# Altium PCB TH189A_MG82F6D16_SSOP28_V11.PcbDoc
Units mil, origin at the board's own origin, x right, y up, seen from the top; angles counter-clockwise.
Board outline 2850.39 x 2110.24 mil, 2 copper layers (Top Layer, Bottom Layer); 46 components, 43 nets, 241 pads, 113 vias.
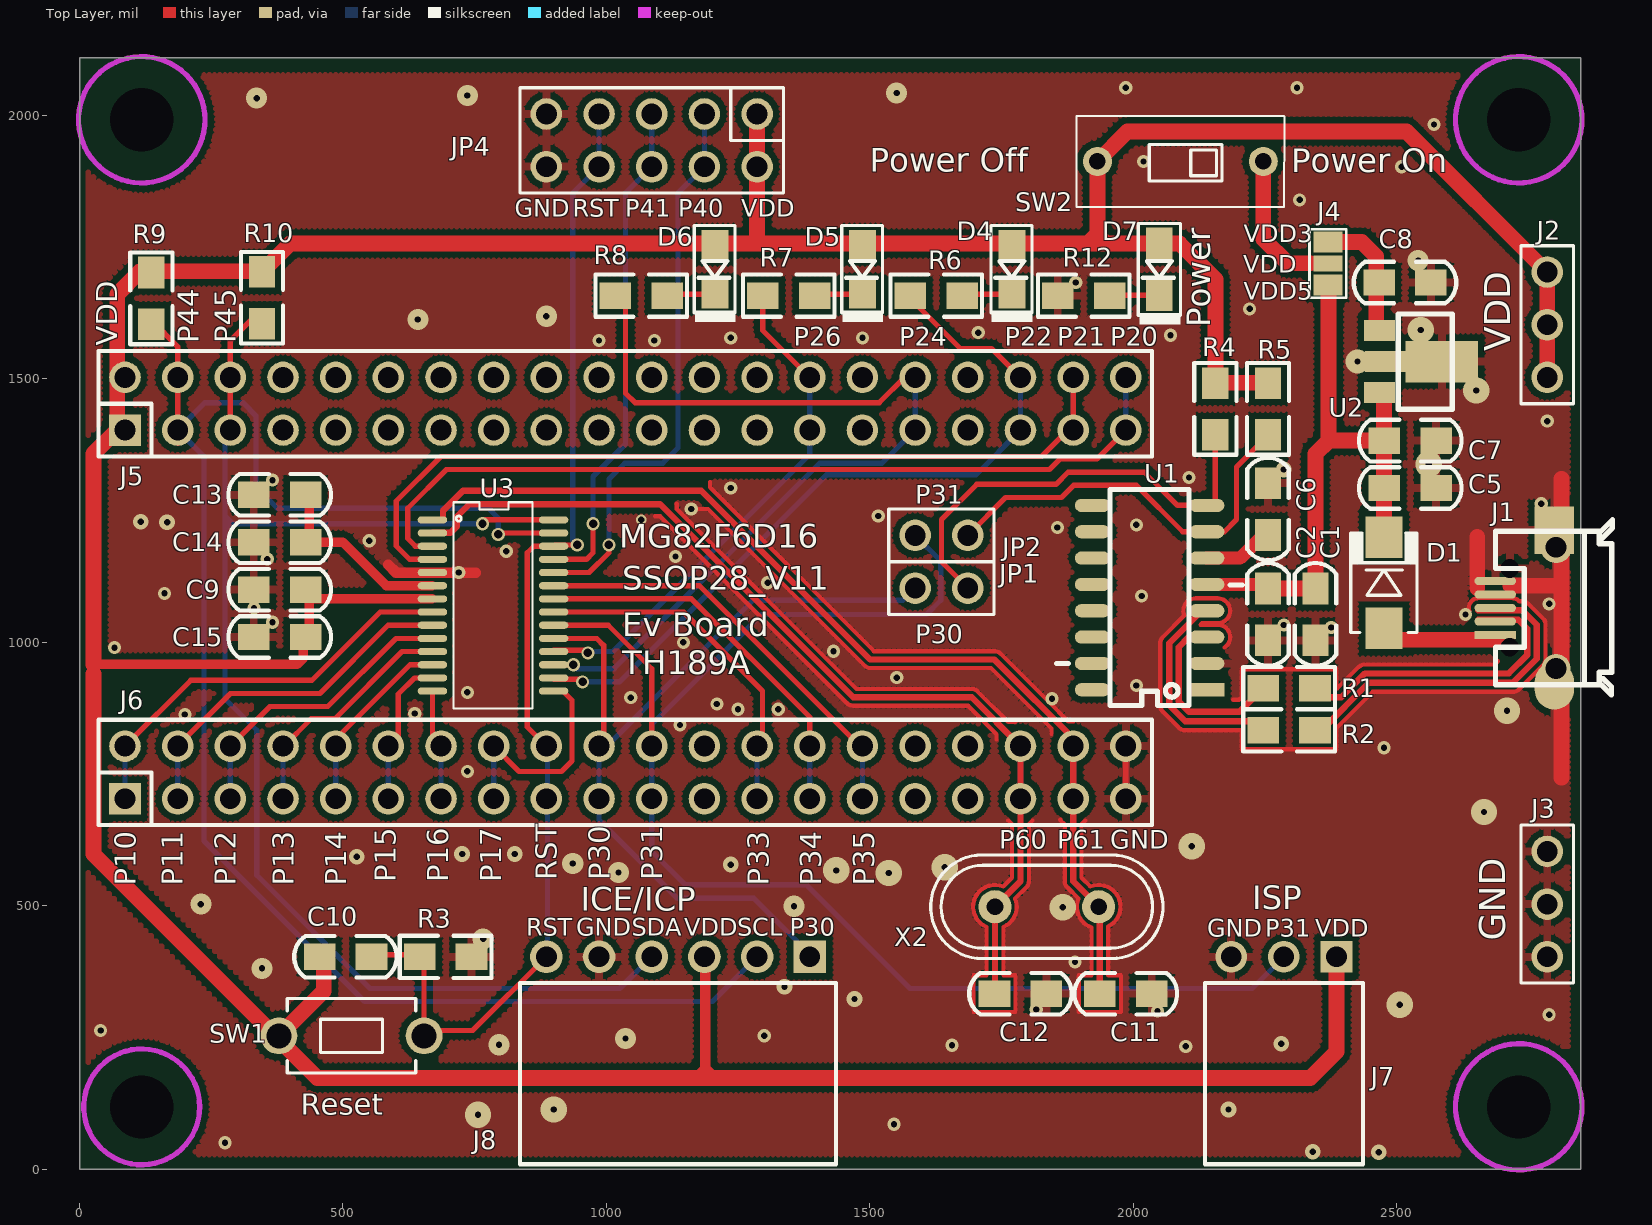
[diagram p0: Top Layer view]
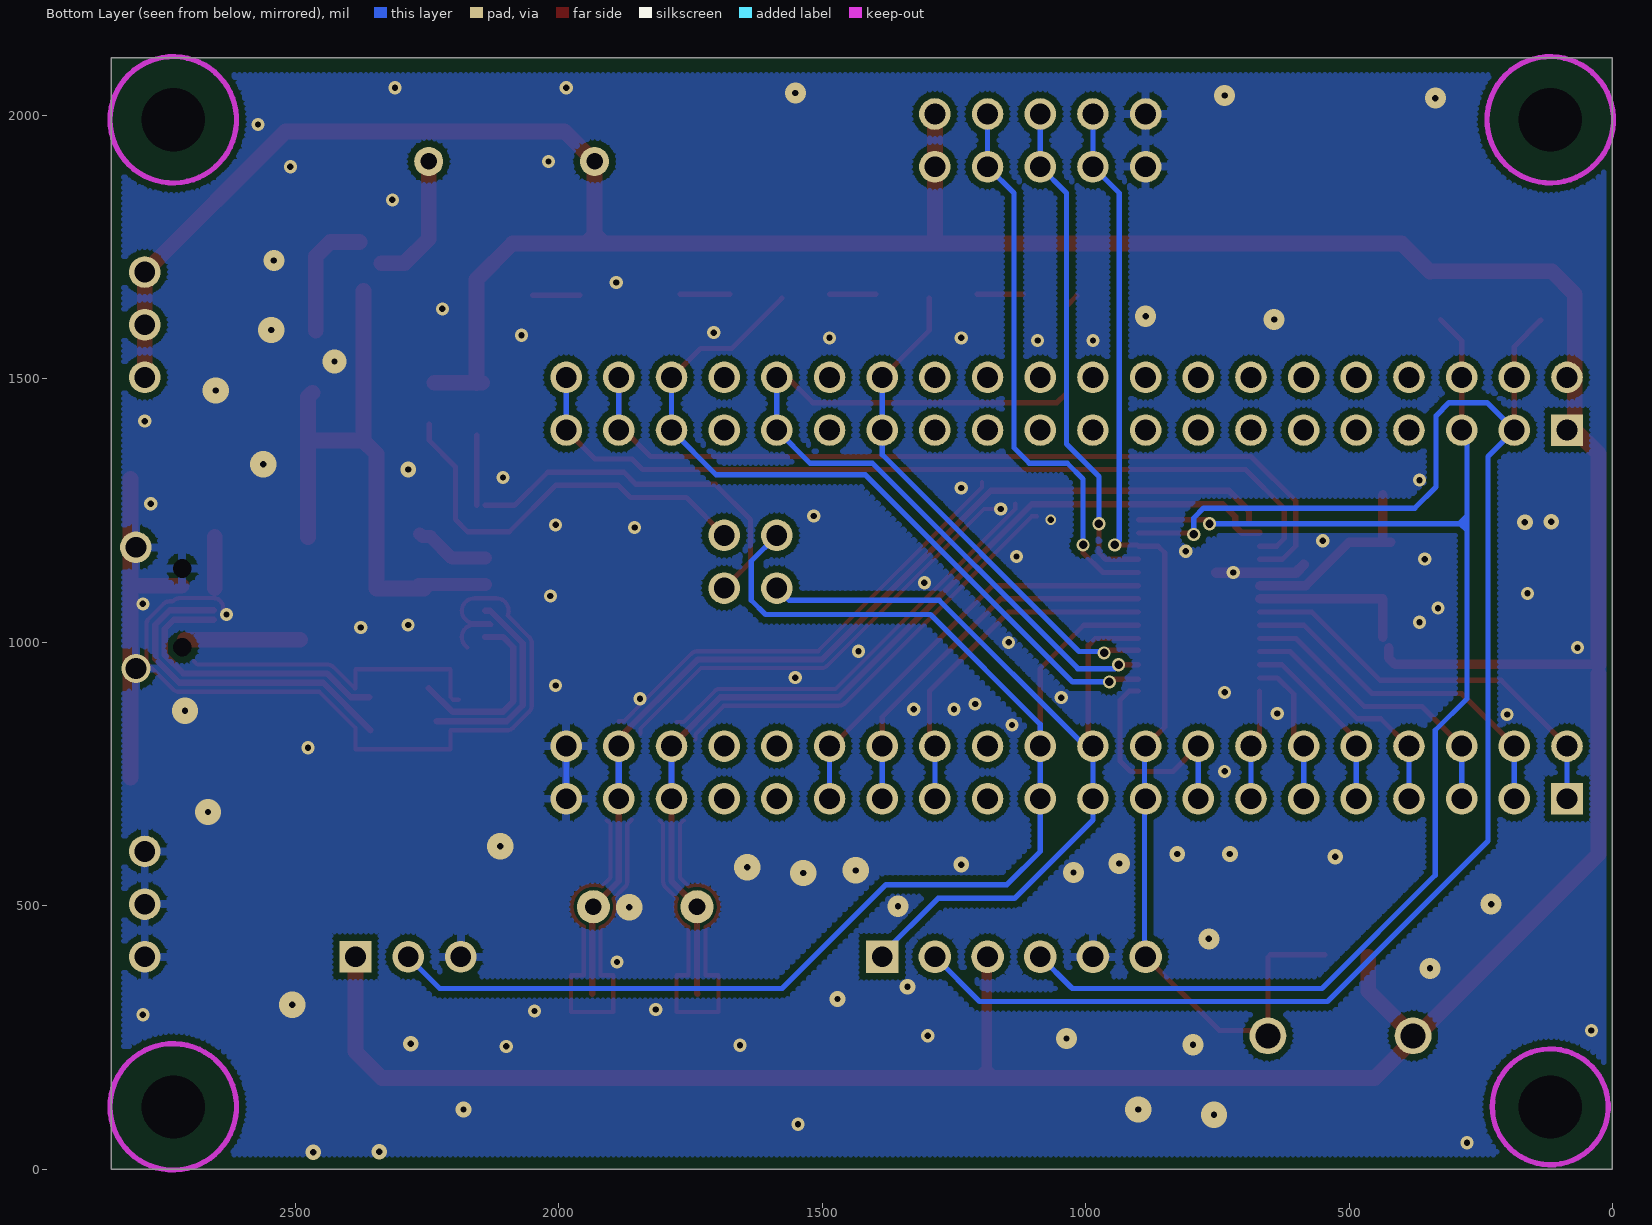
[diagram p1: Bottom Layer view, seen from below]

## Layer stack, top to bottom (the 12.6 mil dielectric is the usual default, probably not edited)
Top Layer: signal copper 1.4
Dielectric: dielectric 12.6, FR-4, Dk 4.8
Bottom Layer: signal copper 1.4

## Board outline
0,0 2850.39,0 2850.39,2110.24 0,2110.24

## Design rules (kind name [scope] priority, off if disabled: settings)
Clearance 12 [All] p1 off: gap=12
Clearance 7 [All] p2 off: gap=7
Clearance 6 [All] p3: gap=6
ComponentClearance [All] p1 off: gap=10 collisioncheckmode=3 verticalgap=10 showdistances=FALSE
HoleSize [All] p1: absolutevalues=TRUE maxlimit=500 minlimit=1 maxpercent=80.000 minpercent=20.000
MinimumSolderMaskSliver [All] p1 off: minsoldermaskwidth=10
PolygonConnect VIA [ISVIA] p1: connectstyle=Direct reliefconductorwidth=10 reliefentries=4 polygonreliefangle="90 Angle"
PolygonConnect [All] p2: connectstyle=Relief reliefconductorwidth=15 reliefentries=4 polygonreliefangle="90 Angle"
RoomDefinition TH189A_MG82F6D16_SSOP28_V11 [InComponentClass('TH189A_MG82F6D16_SSOP28_V11')] p1: confinementstyle=ConfineIn formatcopy=TRUE lockcomponents=FALSE outline -260,-40 2980,-40 2980,2200 -260,2200
RoutingVias [All] p1: holewidth=16 width=25 viastyle="Through Hole" minholewidth=16 minwidth=24 maxholewidth=28 maxwidth=50
SilkToSilkClearance [All] p1 off: silktosilkclearance=10
SilkscreenOverComponentPads [All] p1 off: minsilkscreentomaskgap=10
SolderMaskExpansion [All] p1 off: expansion=4
Width [All] p1: maxlimit=200 minlimit=6 preferedwidth=10
23 further rules are at their usual default settings.

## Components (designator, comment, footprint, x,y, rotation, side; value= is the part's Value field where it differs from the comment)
C1 "4.7uF" 0805C 2346.34,1053 r270 top
C2 "0.1uF" 0805C 2256.34,1053 r90 top
C5 "4.7uF" 0805C 2526.34,1293 r0 top
C6 "1uF" 0805C 2256.34,1253 r270 top
C7 "0.1uF" 0805C 2526.34,1383 r0 top
C8 "4.7uF" 0805C 2516.34,1683 r0 top
C9 "0.1uF" 0805C 380,1100 r0 top
C10 "4.7uF" 0805C 505,403 r0 top
C11 "NC" 0805C 1986.34,333 r180 top
C12 "NC" 0805C 1786.34,333 r180 top
C13 "4.7uF" 0805C 380,1280 r180 top
C14 "0.1uF" 0805C 380,1190 r0 top
C15 "4.7uF" 0805C 380,1010 r180 top
D1 "1N5817" DIODE_SMA 2476.34,1113 r90 top
D4 "Green" 0805D#1 1770,1708 r270 top
D5 "Red" 0805D#1 1486.34,1708 r270 top
D6 "Green" 0805D#1 1206.34,1708 r270 top
D7 "Yellow" 0805D#2 2050,1708 r270 top
J1 "Micro USB" JACK_USB_SMD290X220P065 2687.8,1065.28 r180 top locked
J2 "CON3" PS3P254 2786.34,1503 r90 top
J3 "CON3" PS3P254 2786.34,603 r270 top
J4 "*" JUMP3_SMD 2370,1719 r90 top
J5 "CON40A" PS20X2P254 86.34,1403 r0 top locked
J6 "CON40A" PS20X2P254 86.34,703 r0 top locked
J7 "*" PS3P254f_90 2386.34,403 r180 top
J8 "*" PS6P254F_90 1386.34,403 r180 top
JP1 "JUMPER2" PS2P254 1586.34,1103 r0 top
JP2 "JUMPER2" PS2P254 1586.34,1203 r0 top
JP4 "CON5X2" PS5X2P254 1286.34,2003 r180 top
R1 "22" 0805R 2296.34,913 r180 top
R2 "22" 0805R 2296.34,833 r180 top
R3 "47K" 0805R 695,403 r180 top
R4 "4.7K" 0805R 2156.34,1443 r270 top
R5 "4.7K" 0805R 2256.34,1443 r270 top
R6 "1K" 0805R 1626.34,1658 r0 top
R7 "1K" 0805R 1346.34,1658 r0 top
R8 "1K" 0805R 1066.34,1658 r0 top
R9 "4.7K" 0805R 136.34,1653 r90 top
R10 "4.7K" 0805R 346.34,1654.34 r90 top
R12 "1K" 0805R 1906.34,1658 r0 top
SW1 "SW TACT-SPST" SW_T_2P 516.34,253 r0 top
SW2 "-" DIP2_SW 2247.38,1913 r180 top
U1 "MA111AS16" SO16_150P127 2031.5,1085 r180 top
U2 "AIC1734-33(SOT-89)" SOT89 2468.23,1533 r270 top
U3 "MG82F6D16" SSOP28_150P0635 785,1070 r270 top
X2 "NC" X49U 1836.34,498 r180 top

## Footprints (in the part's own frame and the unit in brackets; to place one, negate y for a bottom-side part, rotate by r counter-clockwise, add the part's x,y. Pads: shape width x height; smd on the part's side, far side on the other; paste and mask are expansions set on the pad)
0805C [mil]
  rect 60x50 smd: 1(-49.21,0) 2(49.21,0)
  silkscreen extent -97,-39 97,39
0805D#1 [mm]
  rect 1.4x1.3 smd: 1(-1.192,0) 2(1.192,0)
  silkscreen extent -2.12,-1 2.53,0.99
0805D#2 [mm]
  rect 1.524x1.27 smd: 1(-1.25,0) 2(1.25,0)
  silkscreen extent -2.21,-1.02 2.66,1.02
0805R [mil]
  rect 60x50 smd: 1(-49.21,0) 2(49.21,0)
  silkscreen extent -87,-40 87,40
DIODE_SMA [mm]
  rect 2x1.8 smd: 1(-2.2,0) 2(2.2,0)
  silkscreen extent -2.4,-1.6 2.44,1.6
DIP2_SW [mm]
  round 1.4 hole 0.8: 1(0,0) 2(8,0)
  silkscreen extent -1.02,-2.2 9.02,2.2
JACK_USB_SMD290X220P065 [mm]
  rect 1.9x1.8 on Mech2: 0(-2.85,-1.15) 0(-2.85,1.15)
  round 0.8 hole 0.9 unplated: 1(-0.7,1.9) 5(-0.7,-1.9)
  rect 2x0.4 smd: 1(0,1.3)
  oval 2x0.4 smd: 2(0,0.65) 3(0,0) 4(0,-0.65) 5(0,-1.3)
  round 1.524 hole 1: 5(-2.931,-2.921)
  rect 1.9x2.3 smd: 5(-2.85,-3.75)
  round 1.397 hole 1: 6(-2.931,2.921)
  oval 1.9x2.3 smd: 6(-2.85,3.75)
  silkscreen extent -5.65,-4.25 -0.01,4.2
JUMP3_SMD [mil]
  rect 40x55 smd: 1(-41,0) 3(41,0)
  rect 30x55 smd: 2(0,0)
  silkscreen extent -65,-35 65,35
PS2P254 [mil]
  round 60 hole 39.37: 1(0,0) 2(100,0)
  silkscreen extent -50,-50 150,50
PS3P254 [mil]
  round 60 hole 39.37: 1(0,0) 2(100,0) 3(200,0)
  silkscreen extent -50,-50 250,50
PS3P254f_90 [mil]
  rect 60x60 hole 39.37: 1(0,0)
  round 60 hole 39.37: 2(100,0) 3(200,0)
  silkscreen extent -50,50 250,394
PS5X2P254 [mil]
  round 60 hole 39.37: 1(0,0) 2(0,100) 3(100,0) 4(100,100) 5(200,0) 6(200,100) 7(300,0) 8(300,100) 9(400,0) 10(400,100)
  silkscreen extent -50,-50 450,150
PS6P254F_90 [mil]
  rect 62x62 hole 39.37: 1(0,0)
  round 62 hole 39.37: 2(100,0) 3(200,0) 4(300,0) 5(400,0) 6(500,0)
  silkscreen extent -50,50 550,394
PS20X2P254 [mil]
  rect 60x60 hole 39.37: 1(0,0)
  round 60 hole 39.37: 2(0,100) 3(100,0) 4(100,100) 5(200,0) 6(200,100) 7(300,0) 8(300,100) 9(400,0) 10(400,100) 11(500,0) 12(500,100) 13(600,0) 14(600,100) 15(700,0) 16(700,100) 17(800,0) 18(800,100) 19(900,0) 20(900,100) 21(1000,0) 22(1000,100) 23(1100,0) 24(1100,100) 25(1200,0) 26(1200,100) 27(1300,0) 28(1300,100) 29(1400,0) 30(1400,100) 31(1500,0) 32(1500,100) 33(1600,0) 34(1600,100) 35(1700,0) 36(1700,100) 37(1800,0) 38(1800,100) 39(1900,0) 40(1900,100)
  silkscreen extent -50,-50 1950,150
SO16_150P127 [mil]
  rect 67x25 smd: 1(-108.5,175)
  oval 67x25 smd: 2(-108.5,125) 3(-108.5,75) 4(-108.5,25) 5(-108.5,-25) 6(-108.5,-75) 7(-108.5,-125) 8(-108.5,-175) 9(108.5,-175) 10(108.5,-125) 11(108.5,-75) 12(108.5,-25) 13(108.5,25) 14(108.5,75) 15(108.5,125) 16(108.5,175)
  silkscreen extent -176,-205 177,205
SOT89 [mm]
  rect 1.016x1.5 smd: 1(-1.5,0) 3(1.5,0)
  rect 2x3.5 smd: 2(0,3)
  rect 1.016x2.6 smd: 2(0,0.6)
  silkscreen extent -2.3,0.9 2.3,3.5
SSOP28_150P0635 [mil]
  oval 13.5x56 smd: 1(-162.5,-115) 2(-137.5,-115) 3(-112.5,-115) 4(-87.5,-115) 5(-62.5,-115) 6(-37.5,-115) 7(-12.5,-115) 8(12.5,-115) 9(37.5,-115) 10(62.5,-115) 11(87.5,-115) 12(112.5,-115) 13(137.5,-115) 14(162.5,-115) 15(162.5,115) 16(137.5,115) 17(112.5,115) 18(87.5,115) 19(62.5,115) 20(37.5,115) 21(12.5,115) 22(-12.5,115) 23(-37.5,115) 24(-62.5,115) 25(-87.5,115) 26(-112.5,115) 27(-137.5,115) 28(-162.5,115)
  silkscreen extent -196,-75 196,75
SW_T_2P [mil]
  round 70 hole 47.24: 1(-137.79,0) 2(137.79,0)
  silkscreen extent -122,-71 122,71
X49U [mm]
  round 1.6 hole 0.8: 1(-2.5,0) 2(2.5,0)
  silkscreen extent -5.6,-2.5 5.6,2.5

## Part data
C1 C5 C8 C13 C15: library part CAP
C2 C6 C7 C9 C14: library part "CAP NP"
C10: library part C
C11 C12: library part "C NP"
D1: library part DIODE_ZD, "Schottky Diode"
D4 D5 D6 D7: library part LED
J1 J8: library part CON6
J4 J7: library part CON3
R1 R2 R3 R9 R10: library part R
R4 R5 R6 R7 R8: library part R_Dup1
R12: library part R_Dup2
SW2: library part SW-2
U2: library part AIC1734-33(SOT-89)_0
U3: library part MG82FG5Dxx_SSOP-28
X2: library part CRYSTAL

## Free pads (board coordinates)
  round 40 hole 120 unplated: 0(118.11,118.11) 0(118.11,1992.13) 0(2732.28,118.11) 0(2732.28,1992.13)

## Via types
v1: diameter 25, hole 12, Top Layer to Bottom Layer, tented both sides, 63 vias
v2: diameter 40, hole 12, Top Layer to Bottom Layer, tented both sides, 14 vias
v3: diameter 50, hole 12, Top Layer to Bottom Layer, tented both sides, 13 vias
v4: diameter 30, hole 12, Top Layer to Bottom Layer, tented both sides, 13 vias
v5: diameter 25, hole 16, Top Layer to Bottom Layer, tented both sides, 8 vias
v6: diameter 20, hole 12, Top Layer to Bottom Layer, tented both sides, 1 vias
v7: diameter 45, hole 12, Top Layer to Bottom Layer, tented both sides, 1 vias

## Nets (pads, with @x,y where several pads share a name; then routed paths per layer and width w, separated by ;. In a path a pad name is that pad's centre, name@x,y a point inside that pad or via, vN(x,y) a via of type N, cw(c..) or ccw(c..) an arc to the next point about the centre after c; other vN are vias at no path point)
D+: R2.2 U1.4 | length 391
  Top Layer w12: U1.4 2130.66,1060 2068.66,998 2068.66,880.22 2098.88,850 R2.2@2232.37,850
D-: R1.2 U1.3 | length 347.4
  Top Layer w12: 2106.39,1010.27 2086.66,990.54 2086.66,887.68 2106.34,868 2202.13,868 R1.2 ; U1.3@2110.66,1010 U1.3
GND_POWER: C1.2 C2.1 C5.2 C6.1 C7.2 C8.2 C9.1 C11.1 C12.1 C13.2 C14.1 C15.2 J1.4 J1.5 J1.6 J3.1 J3.2 J3.3 J6.39 J6.40 J7.3 J8.5 JP4.9 JP4.10 R3.1 R12.1 U1.2 U2.2 U3.5 | length 8829.7
  Top Layer w8: 1092.62,1239.19 1102.52,1239.19 1457.35,884.36 ccw(c1468.68,895.66) 1468.68,879.66 ; 1133.87,1263 1133.87,1253.1 1475.31,911.66 1693.68,911.66 ; v1(1161.34,1253) 1192.97,1253 1490.01,955.96 ccw(c1501.34,967.26) 1501.34,951.26 ; 1196.86,1304.26 1196.86,1294.36 1507.97,983.26 1737.08,983.26 ; 1457.37,884.35 ccw(c1468.68,895.66) 1468.68,879.66 ; 1490.03,955.95 ccw(c1501.34,967.26) 1501.34,951.26 ; 1741.09,815.72 1741.09,825.62 1687.05,879.66 1468.68,879.66 ; 1763.34,662.01 1770.34,655.01 1770.34,553.05 1753.67,536.39 ccw(c1737.91,498) 1721.91,459.71 1721.91,368 1697.13,368 1697.13,298 1777.13,298 1777.13,368 1753.91,368 1753.91,459.71 ccw(c1737.91,498) 1770.34,472.11 ccw(c1737.91,498) 1779.41,498 ccw(c1737.91,498) 1776.3,513.76 1797.64,535.1 ; 1776.34,848.92 1763.04,848.92 1705.01,906.96 ; 1809.34,662.01 1802.34,655.01 1802.34,546.42 ; 1845.52,826.29 1845.52,836.19 1730.45,951.26 1501.34,951.26 ; 1861.66,663 1870.34,654.32 1870.34,546.42 ; 1886.87,850 1876.97,850 1840.15,886.81 1748.41,978.56 ; 1909.34,662.01 1902.34,655.01 1902.34,553.05 1919,536.39 cw(c1934.76,498) 1976.26,498 cw(c1934.76,498) 1953.13,460.79 1953.13,368 1977.13,368 1977.13,298 1897.13,298 1897.13,368 1921.13,368 1921.13,458.81 cw(c1934.76,498) 1902.34,472.11 cw(c1934.76,498) 1896.38,513.76 1875.04,535.1 ; 2056.64,1010.02 ccw(c2068.66,998) 2051.66,998 ; 2173.48,990.08 ccw(c2161,1010) 2184.5,1010 ccw(c2161,1010) 2161,1033.5 2128.2,1033.5 2131.2,1036.5 2161,1036.5 ccw(c2161,1060) 2184.5,1060 ccw(c2161,1060) 2161,1083.5 2119,1083.5 ccw(c2119,1060) 2097.39,1050.77 2056.66,1010.04 ccw(c2068.66,998) 2051.66,998 ; 2190.5,891 2201.08,891 2206.13,896.04 2206.13,949 2386.55,949 2386.55,913 ; 2388.3,913 2428.3,953 cw(c2440.34,941) 2440.34,958 ; 2428.32,953.02 cw(c2440.34,941) 2440.34,958 ; v1@2638.44,1059.18 cw(c2656.3,1065.28) 2656.3,1084.15 2687.8,1084.15 2719.29,1084.15 cw(c2719.29,1065.28) 2733.23,1078 2738.79,1078 ; 2692.89,964 2686.89,958 2440.34,958 ; 1693.68,911.66 cw(c1693.68,895.66) 1705.01,906.96 ; 1693.68,911.66 cw(c1693.68,895.66) 1704.99,906.97 ; 1737.08,983.26 cw(c1737.08,967.26) 1748.39,978.57 ; 1737.08,983.26 cw(c1737.08,967.26) 1748.41,978.56 ; 1797.64,535.1 ccw(c1786.34,546.42) 1802.34,546.42 ; 1797.65,535.11 ccw(c1786.34,546.42) 1802.34,546.42 ; 1870.34,546.42 ccw(c1886.34,546.42) 1875.03,535.11 ; 1870.34,546.42 ccw(c1886.34,546.42) 1875.04,535.1 ; 2051.66,880.22 ccw(c2068.66,880.22) 2056.66,868.18 ; 2051.66,880.22 ccw(c2068.66,880.22) 2056.64,868.2 ; 2051.66,880.22 2051.66,998 ; 2056.66,868.18 2086.84,838 ; 2086.86,837.98 ccw(c2098.88,850) 2098.88,833 ; 2086.84,838 ccw(c2098.88,850) 2098.88,833 ; 2098.88,833 2206.13,833 2206.13,797 2386.55,797 2386.55,837.72 2454.84,906 2720.79,906 ; 2720.79,906 ccw(c2720.79,923) 2732.83,911 ; 2720.79,906 ccw(c2720.79,923) 2732.82,910.98 ; 2732.83,911 2769.74,947.9 J1.6@2778.34,956.5 ; 2738.79,1078 cw(c2738.79,1061) 2750.83,1073 ; 2738.79,1078 cw(c2738.79,1061) 2750.82,1073.02 ; 2750.83,1073 2778.34,1045.5 ; J1.6@2778.34,956.5 ccw(c2766.34,968.54) J1.6@2783.34,968.54 ; J1.6@2778.36,956.52 ccw(c2766.34,968.54) J1.6@2783.34,968.54 ; 2778.36,1045.48 cw(c2766.34,1033.46) 2783.34,1033.46 ; 2778.34,1045.5 cw(c2766.34,1033.46) 2783.34,1033.46 ; J1.6@2783.34,968.54 2783.34,1033.46
  Top Layer w10: J6.39 J6.40
  Top Layer w20: 586.34,1147 600.84,1132.5 U3.5 v1(720,1132.5) 752.5,1132.5
  Top Layer w30: 2653.66,1102.91 2653.66,1116.46 2653.66,1200 ; 2716.34,1107.32 2813.43,1107.32 ; 2813.66,743 2813.66,917.64 2813.66,950.28 2813.66,1073 2813.66,1180.28 2813.66,1212.91 2813.66,1310
  Bottom Layer w10: J6.39 J6.40
  other v1: 276.34,50 1546.34,85 2100,233 1656.34,235 1300,253 40,263 2790,293 2046.34,300 1816.34,303 1890,393 736.34,755 2476.34,800 1140,843 200,863 636.34,865 1250,873 1326.34,873 1210,883 1846.34,893 1046.34,895 736.34,905 2006.34,918 1551.34,933 1431.34,983 66.34,990 1146.34,1000 2376.34,1028 2286.34,1033 366.34,1038 2631.34,1053 331.34,1065 2790,1073 2016.34,1088 161.34,1093 1306.34,1113 356.34,1158 1131.34,1163 810,1173 550,1193 1856.34,1218 2006.34,1223 1516.34,1240 2775,1263 1236.34,1293 366.34,1308 2106.34,1313 2786.34,1420 986.34,1573 1091.34,1573 1236.34,1578 1486.34,1578 2071.34,1583 1706.34,1588 2221.34,1633 1891.34,1683 2316.34,1840 2510,1903 2020,1913 2571.34,1983 1986.34,2053 2311.34,2053
  other v2: 796.34,236 1036.34,248 346.34,381 766.34,437 1356.34,499 230.34,503 1023.34,563 936.34,580 642.34,1613 886.34,1619 2541.34,1725 336.34,2033 736.34,2038 1551.34,2043
  other v3: 756.34,103 900.34,113 2506.34,312 1866.34,497 1536.34,562 1436.34,567 1642.34,573 2111.34,613 2666.34,678 2710,870 2561.34,1338 2651.34,1478 2546.34,1593
  other v4: 2466.34,32 2341.34,33 2181.34,113 2281.34,238 1471.34,323 1338.34,346 1236.34,578 526.34,593 726.34,598 826.34,598 166.34,1228 116.34,1229 2286.34,1328
  other v6: 1066.34,1233
  other v7: 2426.34,1533
MA111_RX: JP2.2 R5.2 U1.7 | length 796.8
  Top Layer w10: JP2.2 1758.24,1274.9 1863.95,1274.9 1887.05,1298 2006.34,1298 2094.34,1210 U1.7 2173.34,1210 2196.34,1233 2196.34,1333 2246.34,1383 R5.2@2246.34,1413.79
MA111_TX: JP1.2 R4.2 U1.8 | length 851.5
  Top Layer w10: JP1.2 1636.34,1153 1636.34,1233 1703.24,1299.9 1853.6,1299.9 1876.69,1323 2021.34,1323 2084.34,1260 U1.8 ; U1.8@2156.34,1260 R4.2
NetC6_2: C6.2 U1.6 | length 143.2
  Top Layer w25: U1.6 2203.34,1160 2244.23,1200.89 2259.23,1200.89 C6.2@2264.23,1205.89
NetC13_1: C13.1 C14.2 U3.6 | length 372.8
  Top Layer w18: C14.2@421.34,1190 C14.2 C14.2@436.34,1190 ; C13.1@436.34,1280 C14.2@436.34,1190 ; U3.6 582.5,1107.5 500,1190 C14.2@436.34,1190
NetD1_1: D1.1 J1.1 | length 218.7
  Top Layer w30: D1.1@2491.34,1005 J1.1@2710,1005
NetD4_2: D4.2 R6.2 | length 94.4
  Top Layer w10: R6.2@1675.63,1661.08 D4.2
NetD5_2: D5.2 R7.2 | length 87.7
  Top Layer w10: R7.2@1398.63,1661.08 D5.2
NetD6_2: D6.2 R8.2 | length 87.7
  Top Layer w10: R8.2@1118.63,1661.08 D6.2
NetD7_2: D7.2 R12.2 | length 89.9
  Top Layer w10: R12.2@1960.06,1658.79 D7.2
NetJ1_2: J1.2 R1.1 | length 571.2
  Top Layer w12: R1.1@2360.3,896 2395.34,896 2440.34,941 2713.34,941 2748.34,976 2748.34,1026 2731.34,1043 J1.2@2655.34,1043
NetJ1_3: J1.3 R2.1 | length 652
  Top Layer w12: R2.1@2357.79,833 2447.79,923 2720.79,923 2766.34,968.54 2766.34,1033.46 2738.79,1061 J1.3@2655.34,1061
NetJ4_2: J4.2 SW2.1 | length 256.1
  Top Layer w30: SW2.1 2247.38,1765.62 2293.5,1719.5 2337,1719.5
P10: J6.1 J6.2 U3.8 | length 789.1
  Top Layer w10: J6.2 211.34,928 441.34,928 570.84,1057.5 U3.8
  Bottom Layer w10: J6.1 J6.2
P11: J6.3 J6.4 U3.9 | length 678.7
  Top Layer w10: J6.4 286.34,903 456.34,903 585.84,1032.5 U3.9
  Bottom Layer w10: J6.3 J6.4
P12: J6.5 J6.6 U3.10 | length 568.4
  Top Layer w10: J6.6 361.34,878 471.34,878 600.84,1007.5 U3.10
  Bottom Layer w10: J6.5 J6.6
P13: J6.7 J6.8 U3.11 | length 458
  Top Layer w10: J6.8 388,803 440,855 485,855 612.5,982.5 U3.11
  Bottom Layer w10: J6.7 J6.8
P14: J6.9 J6.10 U3.12 | length 355.5
  Top Layer w10: J6.10 486.34,816.34 627.5,957.5 U3.12
  Bottom Layer w10: J6.9 J6.10
P15: J6.11 J6.12 U3.13 | length 284.2
  Top Layer w10: J6.12 605,821.66 605,901.66 635.84,932.5 U3.13
  Bottom Layer w10: J6.11 J6.12
P16: J6.13 J6.14 U3.14 | length 188.2
  Top Layer w10: J6.14@670,819.34 U3.14
  Bottom Layer w10: J6.13 J6.14
P17: J6.15 J6.16 U3.15 | length 489.1
  Top Layer w10: J6.16 834.34,755 915,755 935,775 935,790 ; U3.15 917.5,907.5 935,890 935,790 ; 935,845 935,790
  Bottom Layer w10: J6.15 J6.16
P20: J5.39 J5.40 U3.3 | length 1635.5
  Top Layer w10: U3.3 637.5,1182.5 623,1197 623,1254.66 696.34,1328 1841.34,1328 1861.34,1348 1931.34,1348 J5.39
  Bottom Layer w10: J5.39 J5.40
P21: J5.37 J5.38 U3.4 | length 1705.1
  Top Layer w10: U3.4 626.84,1157.5 601.34,1183 601.34,1268 686.34,1353 1826.34,1353 1876.34,1403 J5.37 J5.38
  Bottom Layer w10: J5.37 J5.38
P22: J5.35 J5.36 R6.1 U3.16 | length 1455.7
  Top Layer w10: U3.16@900,930 v5@955,930 ; R6.1@1577.13,1653 1672.13,1558 1731.34,1558 J5.36
  Bottom Layer w10: v5(955,925) 1025,925 1418,1318 1701.34,1318 J5.35 J5.36
P24: J5.31 J5.32 R8.1 U3.17 | length 1742.4
  Top Layer w10: U3.17 v5(937.5,957.5) ; R8.1 R8.1@1036.34,1638.79 ; R8.1@1036.34,1633.79 1036.34,1473 1054.34,1455 1518.34,1455 1566.34,1503 J5.32
  Bottom Layer w10: v5(937.5,957.5) 945,950 1015,950 1405,1340 1523.34,1340 J5.31 J5.32
P26: J5.27 J5.28 R7.1 U3.18 | length 974.8
  Top Layer w10: U3.18@900,985 v5@965,985 ; R7.1@1297.13,1653 1297.13,1592.21 J5.28
  Bottom Layer w10: v5@965,982.43 1012.43,982.43 1386.34,1356.34 J5.27 J5.28
  other v5: 965,980
P30/RXD: J6.19 J6.20 J8.1 JP1.1 U3.19 | length 1680.3
  Top Layer w10: U3.19 981.84,1007.5 995,994.34 995,811.66 J6.20 988.84,800.5 J6.20@988.84,803
  Bottom Layer w10: J6.20@971.34,818 J6.20 J6.19 986.34,663 1135.34,514 1280.34,514 J8.1@1388.34,406 ; J6.20@1001.34,803 1278.34,1080 1563.34,1080 JP1.1
P31/TXD: J6.21 J6.22 J7.2 JP2.1 U3.20 | length 2751.8
  Top Layer w10: U3.20 1003.78,1032.5 1086.34,949.94 J6.22
  Bottom Layer w10: J6.22@1101.19,788.15 J6.22@1086.34,773.3 ; JP2.1 1635,1154.34 1635,1080 1608,1053 1295,1053 1086.34,844.34 J6.22 J6.22@1086.34,773.3 ; J7.2 2226.34,343 1576.34,343 1379.34,540 1149.34,540 1086.34,603 J6.21 J6.22@1086.34,773.3
P33: J6.25 J6.26 U3.21 | length 648.4
  Top Layer w10: U3.21 1146.84,1057.5 1296.61,907.73 J6.26@1296.61,803
  Bottom Layer w10: J6.25 J6.26@1286.34,788
P34: J6.27 J6.28 U3.22 | length 734.3
  Top Layer w10: U3.22 1161.84,1082.5 1386.34,858 J6.28
  Bottom Layer w10: J6.27 J6.28
P35: J6.29 J6.30 U3.23 | length 812.5
  Top Layer w10: U3.23 1176.84,1107.5 1481.34,803 J6.30
  Bottom Layer w10: J6.29 J6.30
P40: JP4.3 JP4.4 U3.24 | length 1070.8
  Top Layer w10: U3.24 967.5,1132.5 1005,1170 v5(1005,1185)
  Bottom Layer w10: v5(1005,1185) 1005,1310 1035,1340 1107,1340 1136.34,1369.34 1136.34,1853 JP4.4 JP4.3
P41: JP4.5 JP4.6 U3.25 | length 959.3
  Top Layer w10: U3.25 962.5,1157.5 975,1170 v5(975,1225)
  Bottom Layer w10: v5(975,1225) 975,1315 1036.34,1376.34 1036.34,1853 JP4.6 JP4.5
P44: J5.3 J5.4 J8.2 R9.1 U3.27 | length 3225.6
  Top Layer w10: R9.1@136.34,1611.66 186.34,1561.66 J5.4 J5.3 J5.3@186.34,1378 ; v5@795,1207.5 U3.27
  Bottom Layer w10: v5(795,1205) 795,1235.97 776.23,1254.74 375.26,1254.74 335,1295 335,1430 310,1455 238.34,1455 J5.3 236.34,1353 236.34,623 541.34,318 1201.34,318 J8.2 ; J8.2@1288.34,403 J8.2@1288.34,426
P45: J5.5 J5.6 J8.4 R10.1 U3.28 | length 2730
  Top Layer w10: J5.5 J5.6 286.34,1573 R10.1@326.34,1613 ; v5@765,1232.5 U3.28
  Bottom Layer w10: J5.5 276.34,1393 276.34,1240 ; v5(765,1225) 291.34,1225 ; 1029.34,346 J8.4 J8.4@1088.34,405 ; J8.4@1077.84,415.5 J8.4@1088.34,426 ; J8.4@1088.34,406 1025.34,343 551.35,343 336.34,558.01 336.34,833 276.34,893 276.34,1213 ; 276.34,1213 288.34,1225 ; 276.34,1213 276.34,1225 ; 276.34,1225 288.34,1225 ; 276.34,1225 276.34,1240 ; 276.34,1240 289.84,1226.5 ; 288.34,1225 289.84,1226.5 ; 288.34,1225 291.34,1225 ; 289.84,1226.5 291.34,1225
P60: C12.2 J6.35 J6.36 U3.2 X2.2 | length 1930.2
  Top Layer w12: U3.2@670,1208 704.38,1208 716.34,1219.96 716.34,1238.53 740,1262.19 1102.15,1262.19 1468.68,895.66 1693.68,895.66 J6.36 J6.35 1786.34,546.42 X2.2 1737.91,333.79 C12.2
  Bottom Layer w12: J6.35 J6.36
P61: C11.2 J6.37 J6.38 U3.1 X2.1 | length 2025.9
  Top Layer w12: U3.1@690,1232.5 690,1250 728,1288 1180.6,1288 1501.34,967.26 1737.08,967.26 J6.38@1893.84,810.5 ; J6.38 J6.37 1886.34,546.42 X2.1 1937.13,495.64 C11.2
  Bottom Layer w12: J6.37 J6.38
RST: C10.2 J6.17 J6.18 J8.6 JP4.7 JP4.8 R3.2 SW1.2 U3.26 | length 2285.4
  Top Layer w10: C10.2@546.34,406.81 R3.2@649.85,406.81 ; R3.2@654.13,402.53 654.13,263 746.34,263 J8.6 888.34,405 J8.6@888.34,426 ; 850,884.34 850,895 ; J6.18 850,839.34 850,895 ; v5(945,1185) 902.5,1185 U3.26 862.5,1182.5 850,1170 850,895
  Bottom Layer w10: J8.6@888.34,406 J6.18@888.34,801 ; v5(945,1185) 936.34,1193.66 936.34,1853 JP4.8 ; JP4.8@981.34,1908 986.34,1913 JP4.7
VDD: C9.2 C10.1 C15.1 D4.1 D5.1 D6.1 D7.1 J2.1 J2.2 J2.3 J5.1 J5.2 J7.1 J8.3 JP4.1 JP4.2 R4.1 R5.1 R9.2 R10.2 SW1.1 SW2.2 U3.7 | length 9187.6
  Top Layer w10: 1158.34,168 1163.34,173 1188.34,198 1213.34,173 ; 1897.13,1753.79 1900.55,1757.21 1921.34,1778 ; 1932.42,1788 1963.21,1757.21
  Top Layer w18: 26.34,958 413,958 425,970 C15.1@425,990 ; C15.1@436.34,1010 436.34,1082.5 U3.7
  Top Layer w20: 1188.34,180 1188.34,198 J8.3@1188.34,406
  Top Layer w30: 26.34,940 26.34,598 451.34,173 1163.34,173 1213.34,173 2336.34,173 2386.34,223 J7.1 J7.1@2386.34,413 ; 26.34,958 26.34,1357.91 71.43,1403 71.43,1660.97 114.79,1704.34 R10.2@346.34,1704.34 ; R10.2 400,1757.21 1286.34,1757.21 ; SW1.1 463.66,338.12 C10.1@463.66,403 ; SW1.1@382.74,249.56 SW1.1@382.82,252.9 ; 1286.34,1855 JP4.2 ; JP4.1 JP4.2 ; 1932.42,1758.29 1932.42,1788 SW2.2 1989.42,1970 2519,1970 J2.3@2786,1703 ; R4.1@2146.34,1493 R4.1@2156.34,1493 ; R4.1 R4.1@2156.34,1493 ; R5.1@2236.34,1493 R4.1@2156.34,1493 ; J2.1 J2.2 J2.3@2786.34,1702.66 ; 1286.34,1757.21 1900.55,1757.21 1963.21,1757.21 D7.1 2088.21,1757.21 2156.34,1689.08 R4.1@2156.34,1493 ; 1286.34,1757.21 JP4.2 ; J2.3@2786,1703 J2.3@2786.34,1702.66 ; J2.3@2786,1703 J2.3 J2.3@2786.34,1702.66
VDD3: C8.1 J4.3 U2.1 | length 234.7
  Top Layer w30: J4.3@2379,1760 2434.34,1760 2461.89,1732.45 U2.1@2461.89,1592.06
VDD5: C1.1 C2.2 C5.1 C7.1 D1.2 J4.1 U1.5 U2.3 | length 1174
  Top Layer w25: U1.5 C2.2@2266.34,1110
  Top Layer w30: C2.2 C1.1 2346.34,1358 2371.34,1383 J4.1@2371.34,1667.66 ; 2372.13,1383 C7.1@2476.34,1383 ; U2.3 2476.34,1465.83 C7.1@2476.34,1383 ; D1.2 C7.1@2476.34,1383
pads on no net: J1.0 J5.7 J5.8 J5.9 J5.10 J5.11 J5.12 J5.13 J5.14 J5.15 J5.16 J5.17 J5.18 J5.19 J5.20 J5.21 J5.22 J5.23 J5.24 J5.25 J5.26 J5.29 J5.30 J5.33 J5.34 J6.23 J6.24 J6.31 J6.32 J6.33 J6.34 U1.1 U1.9 U1.10 U1.11 U1.12 U1.13 U1.14 U1.15 U1.16

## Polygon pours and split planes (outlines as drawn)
GND_POWER on Top Layer "Bottom Layer-No Net" (hatched 90Degree grid 10 track 10, remove dead copper, pour order 1001): 16.34,27 2826.34,27 2826.34,2078 16.34,2078
GND_POWER on Bottom Layer "Bottom Layer-No Net" (hatched 90Degree grid 10 track 10, remove dead copper, pour order 1001): 16.34,27 2826.34,27 2826.34,2078 16.34,2078

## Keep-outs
Keep-Out Layer:
  circle w10: c2732.28,1992.13 r120
  circle w10: c118.11,118.11 r110
  circle w10: c118.11,1992.13 r120
  circle w10: c2732.28,118.11 r120

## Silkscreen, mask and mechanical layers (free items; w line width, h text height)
Top Overlay:
  text "Power Off" at 1500,1893 h45
  text "Power On" at 2300.65,1892.61 h45
  text "GND" at 826.34,1808 h33
  text "RST" at 936.34,1808 h33
  text "P41" at 1036.34,1808 h33
  text "P40" at 1136.34,1808 h33
  text "VDD" at 1256.34,1808 h33
  text "VDD3" at 2210,1760 h33
  text "VDD" at 2209.58,1702 h33
  text "VDD5" at 2210,1650 h33
  text "Power" at 2146.34,1598 h45 r90
  text "P44" at 226.34,1568 h40 r90
  text "P45" at 296.34,1568 h40 r90
  text "VDD" at 71.34,1563 h40 r90
  text "P26" at 1356.34,1563 h35
  text "P24" at 1556.34,1563 h35
  text "P22" at 1756.34,1563 h35
  text "P21" at 1856.34,1563 h35
  text "P20" at 1956.34,1563 h35
  text "VDD" at 2716.34,1553 h50 r90
  text "P31" at 1586.34,1263 h35
  text "MG82F6D16" at 1024.91,1179.43 h45
  text "SSOP28_V11" at 1029.91,1099.43 h45
  text "Ev Board" at 1029.91,1011.93 h45
  text "P30" at 1586.34,998 h35
  text "TH189A" at 1029.91,939.43 h45
  text "P60" at 1746.34,608 h35
  text "P61" at 1856.34,608 h35
  text "GND" at 1956.34,608 h35
  text "RST" at 906.34,548 h40 r90
  text "P30" at 1006.34,548 h40 r90
  text "P31" at 1106.34,548 h40 r90
  text "P15" at 600.29,544.95 h40 r90
  text "P16" at 700.29,544.95 h40 r90
  text "P17" at 800.29,544.95 h40 r90
  text "P10" at 106.34,538 h40 r90
  text "P11" at 196.34,538 h40 r90
  text "P12" at 296.34,538 h40 r90
  text "P13" at 406.34,538 h40 r90
  text "P14" at 506.34,538 h40 r90
  text "P33" at 1308.34,538 h40 r90
  text "P34" at 1408.34,538 h40 r90
  text "P35" at 1508.34,538 h40 r90
  text "ISP" at 2226.34,493 h45
  text "ICE/ICP" at 951.34,490 h45
  text "RST" at 848.34,443 h33
  text "GND" at 943.34,443 h33
  text "SDA" at 1048.34,443 h33
  text "VDD" at 1148.34,443 h33
  text "SCL" at 1248.34,443 h33
  text "P30" at 1348.34,443 h33
  text "GND" at 2141.34,441 h33
  text "P31" at 2251.34,441 h33
  text "VDD" at 2346.34,441 h33
  text "GND" at 2706.34,433 h50 r90
  text "Reset" at 420,103 h40
Mechanical 1:
  the board outline again, w13
Mechanical 2:
  lines w6: -53.66,303 86.34,303 ; 386.34,2003 386.34,2143 ; 1286.34,2003 1286.34,2143 ; 1486.34,2003 1486.34,2143 ; 2386.34,2003 2386.34,2143 ; 2786.34,603 2926.34,603 ; 2786.34,1503 2926.34,1503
